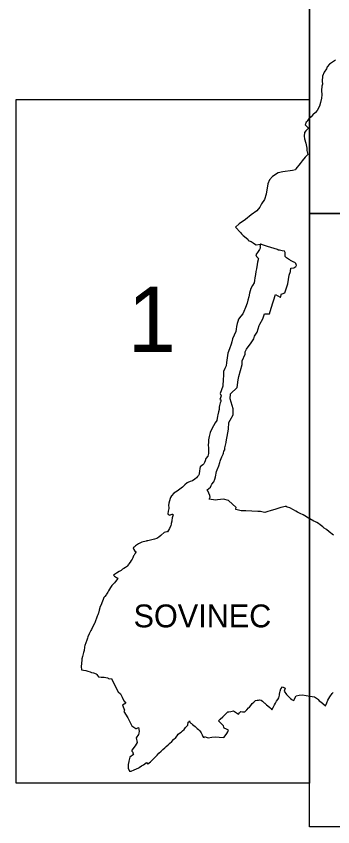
# Model space of a CAD drawing. Extents: x -547343 to -529607, y -1096298 to -1087453.
# Drawn here: x -535596.2 to -535502.1, y -1095855.4 to -1095614.4 of the extents above; entities that cross this region are included whole.
import ezdxf

# ---------------------------------------------------------------- set-up
doc = ezdxf.new("R2010")
doc.units = 0
doc.layers.add('Vrstva 18', color=7, linetype='Continuous')
doc.layers.add('Vrstva 9', color=7, linetype='Continuous')

msp = doc.modelspace()

# ---------------------------------------------------------------- linework, layer by layer
at = {"layer": 'Vrstva 18'}
for points in [[(-535421.82, -1095490.75), (-535508.99, -1095490.75), (-535508.99, -1095673.08), (-535421.82, -1095673.08)], [(-535508.99, -1095639.16), (-535508.99, -1095842.43), (-535596.16, -1095842.43), (-535596.16, -1095639.16)], [(-535421.82, -1095673.08), (-535421.82, -1095855.4), (-535508.99, -1095855.4), (-535508.99, -1095673.08)]]:
    msp.add_lwpolyline(points, close=True, dxfattribs=at)
for points in [[(-535501.3, -1095627.49), (-535502.19, -1095628.02), (-535503.09, -1095628.61), (-535503.81, -1095629.47), (-535503.97, -1095630.08), (-535504.67, -1095631.07), (-535505.13, -1095632.17), (-535505.22, -1095633.7), (-535505.14, -1095634.61), (-535505.36, -1095635.24), (-535505.43, -1095636.44), (-535505.34, -1095637.75), (-535505.44, -1095638.78), (-535505.76, -1095640.05), (-535506.01, -1095641.09), (-535506.75, -1095642.38), (-535507.24, -1095643.06), (-535508.04, -1095643.72), (-535508.52, -1095644.28), (-535509.19, -1095644.94), (-535509.59, -1095645.36), (-535509.75, -1095645.67), (-535510.02, -1095645.94), (-535510.28, -1095646.68), (-535509.94, -1095647.09), (-535509.3, -1095647.65), (-535509.74, -1095648.07), (-535510.14, -1095648.45), (-535510.54, -1095649.01), (-535510.61, -1095650.08), (-535510.54, -1095650.84), (-535510.1, -1095652.15), (-535509.86, -1095653.58), (-535509.77, -1095654.34), (-535509.55, -1095655.47), (-535510.3, -1095656.3), (-535511.22, -1095657.38), (-535511.84, -1095658.15), (-535513.04, -1095659.78), (-535513.22, -1095660.06), (-535514.11, -1095660.26), (-535516.93, -1095660.62), (-535518.33, -1095660.96), (-535520, -1095662.04), (-535520.93, -1095663.02), (-535521.39, -1095664.23), (-535521.92, -1095667.32), (-535522.42, -1095668.89), (-535523.32, -1095670.14), (-535523.78, -1095671.17), (-535524.63, -1095672.22), (-535526.34, -1095673.46), (-535527.99, -1095674.79), (-535529.93, -1095676.12), (-535531, -1095677.09), (-535529.49, -1095678.72), (-535529.18, -1095679.13), (-535528.73, -1095679.61), (-535527.31, -1095680.7), (-535527.2, -1095681.04), (-535526.31, -1095681.42), (-535525.71, -1095681.81), (-535525.37, -1095682.06), (-535524.87, -1095682.41), (-535523.55, -1095682.13), (-535523.8, -1095682.86), (-535523.63, -1095682.89), (-535523.66, -1095683.38), (-535523.85, -1095683.8), (-535524.25, -1095684.39), (-535524.94, -1095685.37), (-535524.76, -1095685.86), (-535524.22, -1095686.44), (-535524.26, -1095686.62), (-535524.3, -1095686.86), (-535524.43, -1095687.49), (-535524.56, -1095688.26), (-535524.79, -1095689.53), (-535524.92, -1095690.25), (-535525.09, -1095691.18), (-535525.23, -1095692.16), (-535525.35, -1095693.02), (-535525.44, -1095693.62), (-535525.98, -1095694.48), (-535526.5, -1095695.34), (-535526.82, -1095696.74), (-535527.07, -1095697.86), (-535527.31, -1095698.8), (-535527.54, -1095699.7), (-535528.06, -1095700.97), (-535528.57, -1095702.2), (-535528.84, -1095702.84), (-535529.4, -1095703.55), (-535530.11, -1095704.43), (-535530.32, -1095705.15), (-535530.51, -1095705.76), (-535530.67, -1095706.66), (-535530.83, -1095707.46), (-535530.95, -1095708.16), (-535531.43, -1095709.22), (-535531.94, -1095710.33), (-535532.09, -1095711.18), (-535532.25, -1095711.94), (-535532.79, -1095713.32), (-535533.32, -1095714.61), (-535533.59, -1095716.66), (-535533.7, -1095717.36), (-535533.83, -1095718.34), (-535534.16, -1095719.13), (-535534.55, -1095720.04), (-535534.61, -1095721.36), (-535534.63, -1095722.29), (-535534.67, -1095723.04), (-535534.73, -1095723.74), (-535534.8, -1095724.43), (-535535.17, -1095725.51), (-535535.55, -1095726.59), (-535535.22, -1095727.22), (-535535.46, -1095727.84), (-535535.68, -1095728.38), (-535535.38, -1095728.42), (-535535.41, -1095728.95), (-535535.55, -1095729.35), (-535535.8, -1095730.13), (-535535.82, -1095730.65), (-535535.85, -1095731.36), (-535536.02, -1095732.03), (-535536.27, -1095732.95), (-535536.35, -1095733.33), (-535536.58, -1095734.57), (-535537.05, -1095735.32), (-535537.57, -1095736.15), (-535538.02, -1095737.06), (-535538.57, -1095738.21), (-535538.65, -1095738.55), (-535538.85, -1095739.38), (-535539.01, -1095740.3), (-535539.07, -1095741.05), (-535539.13, -1095741.96), (-535539.08, -1095742.71), (-535538.99, -1095743.85), (-535539.07, -1095744.39), (-535539.18, -1095745.18), (-535539.82, -1095745.9), (-535540.04, -1095746.59), (-535540.24, -1095747.13), (-535540.38, -1095747.45), (-535540.73, -1095747.76), (-535541.47, -1095748.36), (-535541.62, -1095748.82), (-535541.63, -1095749.03), (-535541.67, -1095749.51), (-535541.83, -1095750.55), (-535542.02, -1095750.94), (-535542.26, -1095751.29), (-535542.55, -1095751.65), (-535543.1, -1095752.08), (-535543.74, -1095752.57), (-535544.46, -1095752.73), (-535545.14, -1095752.99), (-535545.36, -1095753.12), (-535546.02, -1095753.72), (-535546.78, -1095754.45), (-535547.53, -1095755), (-535548.39, -1095755.57), (-535549.34, -1095756.22), (-535549.99, -1095757.04), (-535550.32, -1095757.5), (-535550.45, -1095757.77), (-535550.82, -1095759.19), (-535550.87, -1095759.85), (-535550.8, -1095760.47), (-535550.85, -1095760.8), (-535551.01, -1095761.59), (-535551.11, -1095762.36), (-535551.01, -1095762.43), (-535550.72, -1095762.64), (-535550.72, -1095762.64), (-535550.7, -1095762.65), (-535550.62, -1095762.71), (-535549.83, -1095762.44), (-535549.75, -1095762.49), (-535549.63, -1095762.57), (-535549.56, -1095762.61), (-535549.54, -1095762.63), (-535549.86, -1095763.53), (-535549.92, -1095764.28), (-535549.94, -1095764.48), (-535550.12, -1095765.27), (-535550.15, -1095765.42), (-535550.25, -1095765.84), (-535550.57, -1095766.72), (-535551.17, -1095767.74), (-535551.27, -1095767.7), (-535551.39, -1095767.68), (-535552.19, -1095767.85), (-535553.12, -1095768.67), (-535553.23, -1095768.76), (-535553.81, -1095769.24), (-535554.38, -1095769.65), (-535555.08, -1095769.92), (-535557.1, -1095770.37), (-535557.32, -1095770.42), (-535557.6, -1095770.49), (-535558.86, -1095770.8), (-535559.23, -1095770.96), (-535559.59, -1095771.12), (-535559.85, -1095771.3), (-535560.44, -1095771.7), (-535560.76, -1095771.9), (-535561.16, -1095772.24), (-535561.39, -1095772.43), (-535561.19, -1095772.93), (-535560.92, -1095773.47), (-535560.52, -1095773.61), (-535560.62, -1095773.78), (-535560.8, -1095774.05), (-535560.92, -1095774.24), (-535561.16, -1095774.61), (-535561.28, -1095774.87), (-535561.56, -1095775.42), (-535561.76, -1095775.84), (-535561.99, -1095776.18), (-535562.31, -1095776.68), (-535562.67, -1095777.25), (-535562.84, -1095777.44), (-535563.23, -1095777.9), (-535563.42, -1095778.09), (-535563.74, -1095778.31), (-535564.15, -1095778.59), (-535564.54, -1095778.83), (-535565.01, -1095779.15), (-535565.6, -1095779.53), (-535566.39, -1095780.03), (-535567.27, -1095780.57), (-535567.19, -1095780.65), (-535566.98, -1095780.84), (-535566.41, -1095781.31), (-535565.98, -1095781.52), (-535566.27, -1095781.97), (-535566.62, -1095782.51), (-535566.98, -1095782.88), (-535567.39, -1095783.29), (-535567.75, -1095783.65), (-535567.95, -1095783.95), (-535568.18, -1095784.26), (-535568.43, -1095784.75), (-535568.72, -1095785.28), (-535568.94, -1095785.65), (-535569.34, -1095786.26), (-535569.46, -1095786.42), (-535569.87, -1095786.93), (-535570.12, -1095787.26), (-535570.34, -1095787.84), (-535570.72, -1095788.79), (-535570.97, -1095789.37), (-535571.27, -1095790.06), (-535571.34, -1095790.33), (-535571.5, -1095791), (-535571.73, -1095791.9), (-535571.79, -1095792.05), (-535571.92, -1095792.39), (-535572.1, -1095792.8), (-535572.32, -1095793.39), (-535572.58, -1095794.16), (-535572.78, -1095794.72), (-535572.88, -1095794.94), (-535573.47, -1095796.09), (-535573.81, -1095796.71), (-535574.04, -1095797.04), (-535574.21, -1095797.44), (-535574.49, -1095798.04), (-535574.9, -1095798.95), (-535575.01, -1095799.27), (-535575.23, -1095799.88), (-535575.52, -1095800.66), (-535575.82, -1095801.46), (-535575.88, -1095801.86), (-535575.9, -1095802.14), (-535575.96, -1095802.81), (-535576, -1095803.02), (-535576.14, -1095803.56), (-535576.48, -1095804.79), (-535576.65, -1095805.41), (-535576.69, -1095805.95), (-535576.76, -1095806.61), (-535576.79, -1095806.88), (-535576.87, -1095807.78), (-535576.78, -1095808.68), (-535576.15, -1095808.8), (-535575.48, -1095808.95), (-535574.93, -1095809.14), (-535574.22, -1095809.36), (-535573.82, -1095809.49), (-535573.23, -1095809.67), (-535572.39, -1095809.92), (-535572.23, -1095810.13), (-535572.01, -1095810.44), (-535571.76, -1095810.79), (-535571.54, -1095810.82), (-535570.96, -1095810.88), (-535570.01, -1095810.87), (-535569.06, -1095811.07), (-535568.83, -1095811.18), (-535568.77, -1095811.32), (-535568.56, -1095811.39), (-535567.87, -1095811.29), (-535566.4, -1095814.42), (-535565.89, -1095815.28), (-535565.21, -1095815.89), (-535564.72, -1095816.87), (-535564.14, -1095817.91), (-535563.55, -1095818.6), (-535563.92, -1095818.82), (-535564.09, -1095818.93), (-535564.55, -1095819.21), (-535564.02, -1095820.69), (-535564.16, -1095821.16), (-535562.95, -1095823.01), (-535562.62, -1095823.75), (-535561.86, -1095825.37), (-535561.25, -1095825.73), (-535560.58, -1095826.19), (-535560.4, -1095826.15), (-535559.86, -1095825.88), (-535559.61, -1095826.93), (-535559.72, -1095827.57), (-535559.86, -1095827.96), (-535560.55, -1095828.94), (-535560.2, -1095830.32), (-535560.85, -1095831.36), (-535561.81, -1095832.65), (-535561.79, -1095832.92), (-535561.55, -1095833.25), (-535561.47, -1095833.38), (-535561.4, -1095833.71), (-535561.35, -1095833.95), (-535562.45, -1095834.71), (-535562.74, -1095835.87), (-535562.83, -1095836.55), (-535562.86, -1095836.79), (-535562.86, -1095837.99), (-535562.46, -1095838.85), (-535561.99, -1095838.82), (-535561.14, -1095838.51), (-535559.77, -1095837.82), (-535559.64, -1095837.74), (-535558.95, -1095837.32), (-535558.38, -1095836.94), (-535557.45, -1095836.31), (-535557.24, -1095836.55), (-535557.1, -1095836.71), (-535556.24, -1095836.04), (-535555.58, -1095835.37), (-535555.08, -1095834.87), (-535554.33, -1095834.1), (-535553.76, -1095833.54), (-535553.09, -1095832.88), (-535552.6, -1095832.46), (-535551.99, -1095831.92), (-535551.56, -1095831.54), (-535551.03, -1095831.04), (-535550.58, -1095830.61), (-535549.96, -1095830), (-535549.41, -1095829.47), (-535548.78, -1095828.83), (-535548.38, -1095828.32), (-535548.05, -1095827.89), (-535547.64, -1095827.6), (-535547.15, -1095827.24), (-535546.74, -1095826.89), (-535546.25, -1095826.46), (-535546.07, -1095826.19), (-535545.89, -1095825.86), (-535545.69, -1095825.69), (-535545.51, -1095825.51), (-535545.2, -1095825.2), (-535545.03, -1095824.25), (-535544.82, -1095824.08), (-535544.64, -1095823.93), (-535544.59, -1095824.24), (-535544.25, -1095824.54), (-535544.1, -1095824.68), (-535543.75, -1095824.99), (-535543.41, -1095825.28), (-535543.01, -1095825.61), (-535542.68, -1095825.89), (-535542.39, -1095826.15), (-535542.05, -1095826.45), (-535541.59, -1095826.88), (-535541.25, -1095827.51), (-535540.96, -1095828.04), (-535540.63, -1095828.71), (-535540.33, -1095828.88), (-535540.18, -1095828.58), (-535539.7, -1095828.74), (-535539.14, -1095828.93), (-535538.08, -1095828.78), (-535536.89, -1095828.62), (-535535.89, -1095828.72), (-535534.5, -1095828.87), (-535534.1, -1095828.33), (-535533.61, -1095827.68), (-535533.33, -1095827.13), (-535533.12, -1095826.67), (-535533.67, -1095826.42), (-535534.33, -1095826.11), (-535534.46, -1095825.74), (-535534.58, -1095825.4), (-535534.91, -1095825.08), (-535535.65, -1095824.3), (-535536.07, -1095823.88), (-535535.54, -1095823.38), (-535534.8, -1095822.66), (-535534.22, -1095822.11), (-535533.31, -1095821.25), (-535532.96, -1095821.17), (-535532.4, -1095821.07), (-535531.62, -1095820.95), (-535530.75, -1095821.54), (-535530.14, -1095821.96), (-535529.81, -1095821.56), (-535529.44, -1095821.14), (-535528.92, -1095821.19), (-535528.19, -1095821.25), (-535527.63, -1095820.6), (-535527.15, -1095820.06), (-535526.85, -1095819.82), (-535526.44, -1095819.3), (-535526.01, -1095818.76), (-535525.57, -1095818.32), (-535525.1, -1095817.88), (-535524.57, -1095817.78), (-535524.15, -1095817.71), (-535523.84, -1095817.68), (-535523.37, -1095817.73), (-535523.03, -1095818.02), (-535522.64, -1095818.36), (-535522.45, -1095818.54), (-535522.34, -1095818.62), (-535522.17, -1095818.7), (-535521.79, -1095819.16), (-535521.38, -1095819.47), (-535520.81, -1095819.88), (-535520.52, -1095820.24), (-535520.17, -1095820.65), (-535519.8, -1095819.94), (-535519.38, -1095819.1), (-535519.12, -1095818.61), (-535518.81, -1095818.01), (-535518.46, -1095817.54), (-535518.11, -1095817.06), (-535517.97, -1095816.29), (-535517.91, -1095815.95), (-535517.82, -1095815.49), (-535517.7, -1095815.07), (-535517.5, -1095814.4), (-535517.05, -1095813.8), (-535516.24, -1095814.21), (-535516.56, -1095815.07), (-535515.82, -1095816.02), (-535515.25, -1095816.62), (-535514.66, -1095817.25), (-535514.28, -1095817.55), (-535514.17, -1095817.61), (-535513.67, -1095817.81), (-535513.52, -1095817.41), (-535513.39, -1095817.14), (-535512.97, -1095816.44), (-535512.05, -1095816.31), (-535511.12, -1095816.19), (-535510.06, -1095816.38), (-535508.94, -1095816.56), (-535508.22, -1095816.68), (-535507.49, -1095816.78), (-535506.97, -1095817.13), (-535506.68, -1095817.32), (-535506.46, -1095817.59), (-535506.19, -1095817.9), (-535505.67, -1095818.29), (-535505.09, -1095818.75), (-535504.23, -1095819.41), (-535503.86, -1095818.52), (-535503.57, -1095817.75), (-535502.98, -1095816.76), (-535502.31, -1095815.74), (-535501.94, -1095815.45)], [(-535514.63, -1095689.98), (-535514.58, -1095689.52), (-535514.57, -1095689.33), (-535513.71, -1095689.22), (-535513.13, -1095688.77), (-535512.95, -1095688.58), (-535512.89, -1095688.52), (-535513.13, -1095687.94), (-535513.4, -1095687.6), (-535513.68, -1095687.5), (-535514.04, -1095687.37), (-535514.49, -1095687.16), (-535514.68, -1095686.99), (-535514.91, -1095686.78), (-535515.24, -1095686.65), (-535515.6, -1095686.47), (-535515.9, -1095686.28), (-535516.09, -1095686.05), (-535516.22, -1095685.84), (-535516.27, -1095685.76), (-535516.28, -1095685.55), (-535516.27, -1095685.4), (-535516.26, -1095685.04), (-535516.24, -1095684.66), (-535516.49, -1095684.23), (-535517.17, -1095684.11), (-535517.94, -1095683.98), (-535518.33, -1095683.94), (-535518.36, -1095683.89), (-535518.5, -1095683.75), (-535521.54, -1095682.85), (-535522.73, -1095682.49), (-535523.24, -1095682.27), (-535523.39, -1095682.2), (-535523.55, -1095682.13)], [(-535501.87, -1095768.73), (-535503.22, -1095767.72), (-535503.95, -1095767.03), (-535504.62, -1095766.58), (-535505.1, -1095766.21), (-535505.87, -1095765.59), (-535506.39, -1095765.22), (-535506.8, -1095764.95), (-535507.19, -1095764.76), (-535507.71, -1095764.49), (-535508.96, -1095763.86), (-535509.32, -1095763.63), (-535510.42, -1095762.96), (-535510.9, -1095762.65), (-535511.13, -1095762.54), (-535511.63, -1095762.31), (-535512.22, -1095762.04), (-535512.6, -1095761.85), (-535513.05, -1095761.59), (-535513.75, -1095761.19), (-535514.83, -1095760.59), (-535515.63, -1095760.32), (-535516, -1095760.2), (-535516.12, -1095760.18), (-535516.26, -1095760.2), (-535516.65, -1095760.26), (-535517.08, -1095760.36), (-535517.58, -1095760.5), (-535519.07, -1095760.94), (-535520.66, -1095761.42), (-535521.42, -1095761.66), (-535522.28, -1095761.94), (-535522.82, -1095761.89), (-535523.15, -1095761.79), (-535523.56, -1095761.66), (-535524.34, -1095761.63), (-535526.14, -1095761.55), (-535527.97, -1095761.47), (-535529.32, -1095761.41), (-535530.88, -1095761.05), (-535530.88, -1095760.99), (-535530.87, -1095760.84), (-535530.84, -1095760.43), (-535533.12, -1095758.38), (-535534.58, -1095758), (-535536.33, -1095758.21), (-535536.96, -1095758.28), (-535538.83, -1095757.97), (-535538.75, -1095757.76), (-535538.68, -1095757.58), (-535538.58, -1095757.37), (-535538.68, -1095756.87), (-535539.26, -1095755.5), (-535539.4, -1095755.3), (-535539.43, -1095755.25), (-535538.44, -1095754.4), (-535538.2, -1095753.9), (-535538.03, -1095753.54), (-535537.46, -1095752.8), (-535537.13, -1095752.03), (-535536.99, -1095751.36), (-535536.66, -1095749.75), (-535536.46, -1095749.27), (-535535.96, -1095748.09), (-535535.64, -1095747.07), (-535535.56, -1095746.66), (-535535.48, -1095746.4), (-535535.06, -1095745.42), (-535534.7, -1095744.61), (-535534.61, -1095744.29), (-535534.47, -1095743.69), (-535534.22, -1095743.32), (-535534.15, -1095743.07), (-535534.21, -1095743.07), (-535534.16, -1095742.86), (-535534.14, -1095742.76), (-535533.83, -1095741.16), (-535533.79, -1095740.92), (-535533.28, -1095738.3), (-535533.07, -1095737.14), (-535532.97, -1095735.22), (-535532.56, -1095734.49), (-535531.68, -1095732.9), (-535531.68, -1095731.16), (-535532.61, -1095728.13), (-535532.49, -1095726.69), (-535530.53, -1095724.74), (-535530.19, -1095722.48), (-535530.05, -1095721.53), (-535529.05, -1095717.95), (-535529, -1095716.83), (-535528.18, -1095714.91), (-535528.09, -1095714.2), (-535527.78, -1095713.35), (-535526.4, -1095711.49), (-535525.56, -1095710.35), (-535525.33, -1095709.49), (-535524.62, -1095708.31), (-535524, -1095706.34), (-535523.79, -1095705.99), (-535522.93, -1095704.37), (-535522.41, -1095702.87), (-535522.29, -1095702.88), (-535520.87, -1095702.87), (-535520.42, -1095701.22), (-535519.14, -1095697.13), (-535517.72, -1095697.9), (-535517.61, -1095697.96), (-535517.33, -1095696.97), (-535517.13, -1095696.91), (-535516.32, -1095696.64), (-535515.44, -1095693.97), (-535515.03, -1095691.43), (-535514.65, -1095690.25), (-535514.63, -1095689.98)]]:
    msp.add_lwpolyline(points, dxfattribs=at)
at = {"layer": 'Vrstva 9'}
for points in [[(-535508.99, -1095490.75), (-535421.82, -1095490.75), (-535421.82, -1095673.08), (-535508.99, -1095673.08)], [(-535596.16, -1095639.16), (-535508.99, -1095639.16), (-535508.99, -1095842.43), (-535596.16, -1095842.43)], [(-535508.99, -1095673.08), (-535421.82, -1095673.08), (-535421.82, -1095855.4), (-535508.99, -1095855.4)]]:
    msp.add_lwpolyline(points, close=True, dxfattribs=at)

# ---------------------------------------------------------------- texts
at = {"layer": 'Vrstva 18'}
for s, height, p in [('1', 19.37, (-535563.08, -1095714.19)), ('SOVINEC', 6.799, (-535561.3, -1095796.1))]:
    msp.add_text(s, height=height, dxfattribs=at).set_placement(p)

doc.saveas('drawing.dxf')
